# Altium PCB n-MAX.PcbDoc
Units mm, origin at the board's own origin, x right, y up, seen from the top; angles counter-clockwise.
Board outline 33.02 x 43.18 mm, 4 copper layers (Top Layer, 3.3V_PLANE, GND_PLANE, Bottom Layer); 27 components, 85 nets, 204 pads, 102 vias.
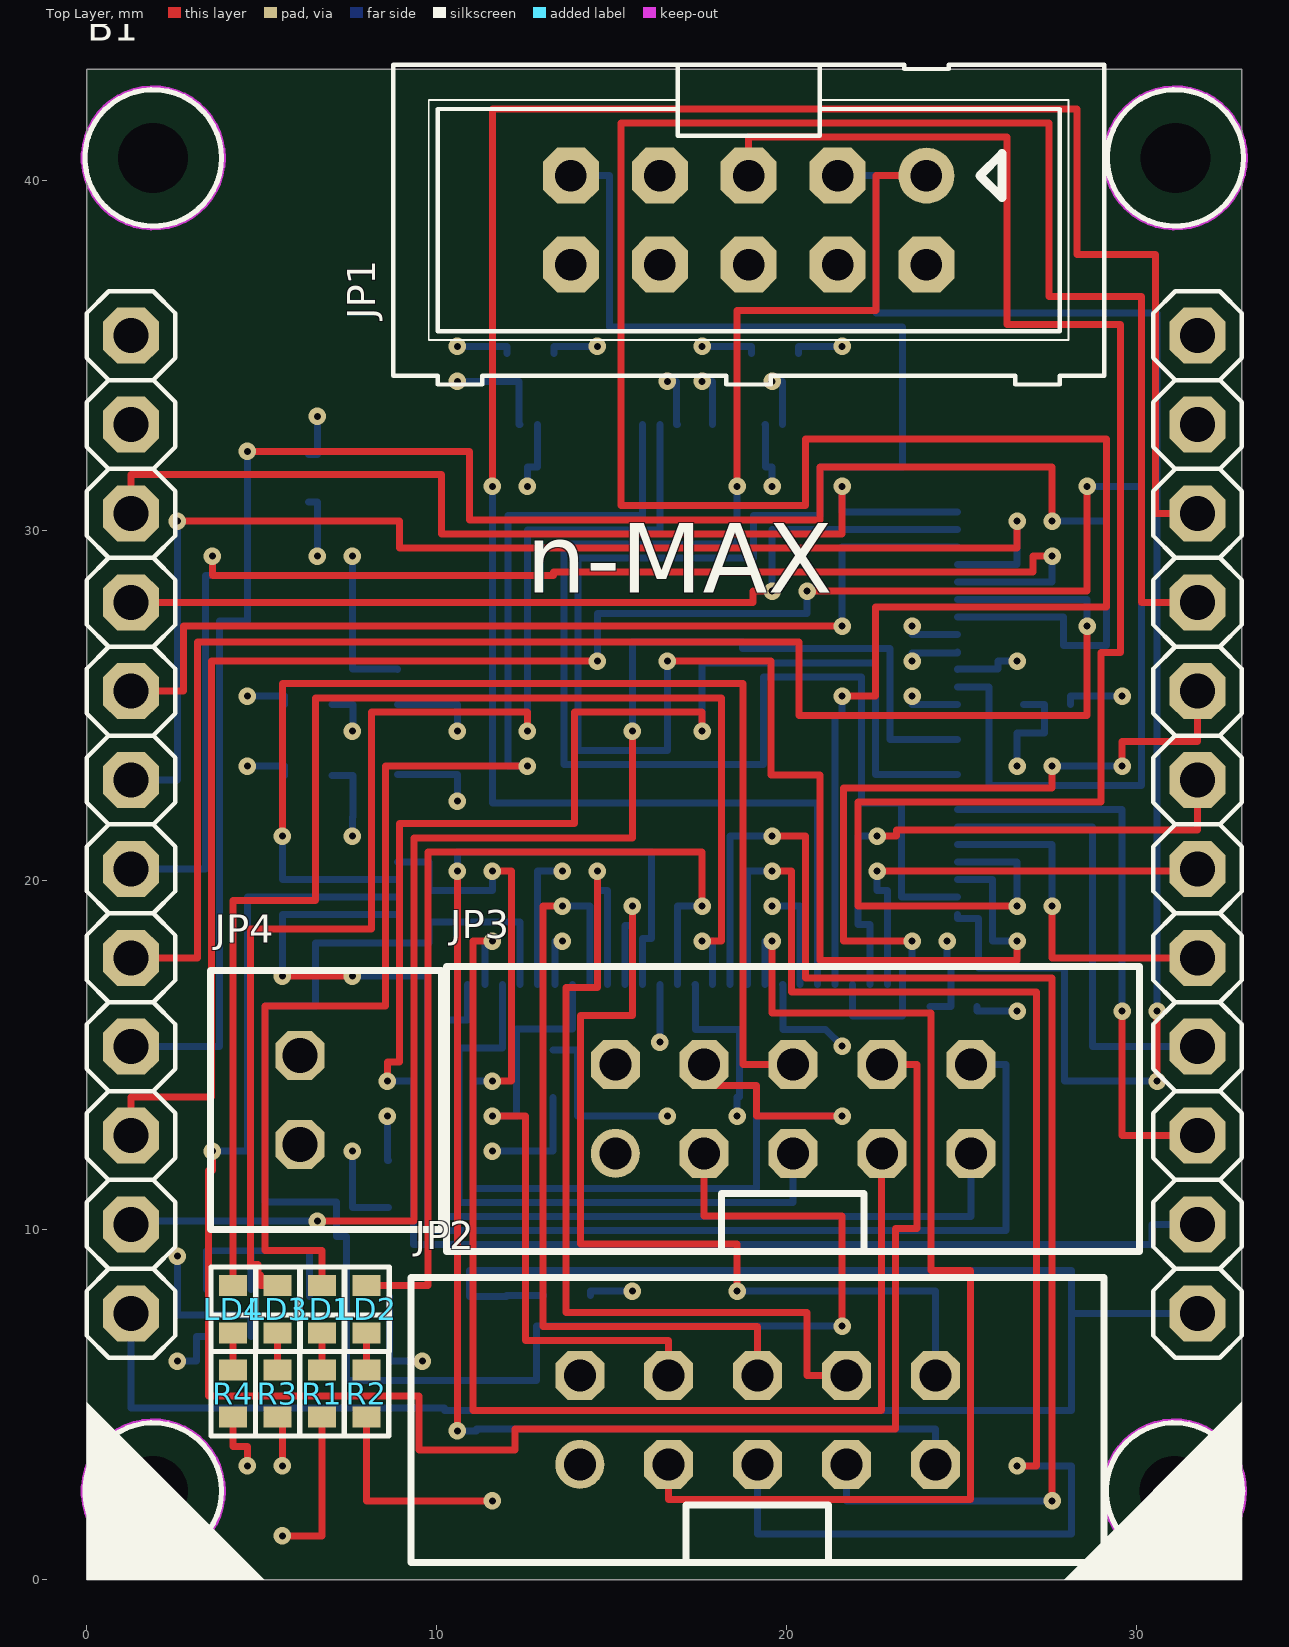
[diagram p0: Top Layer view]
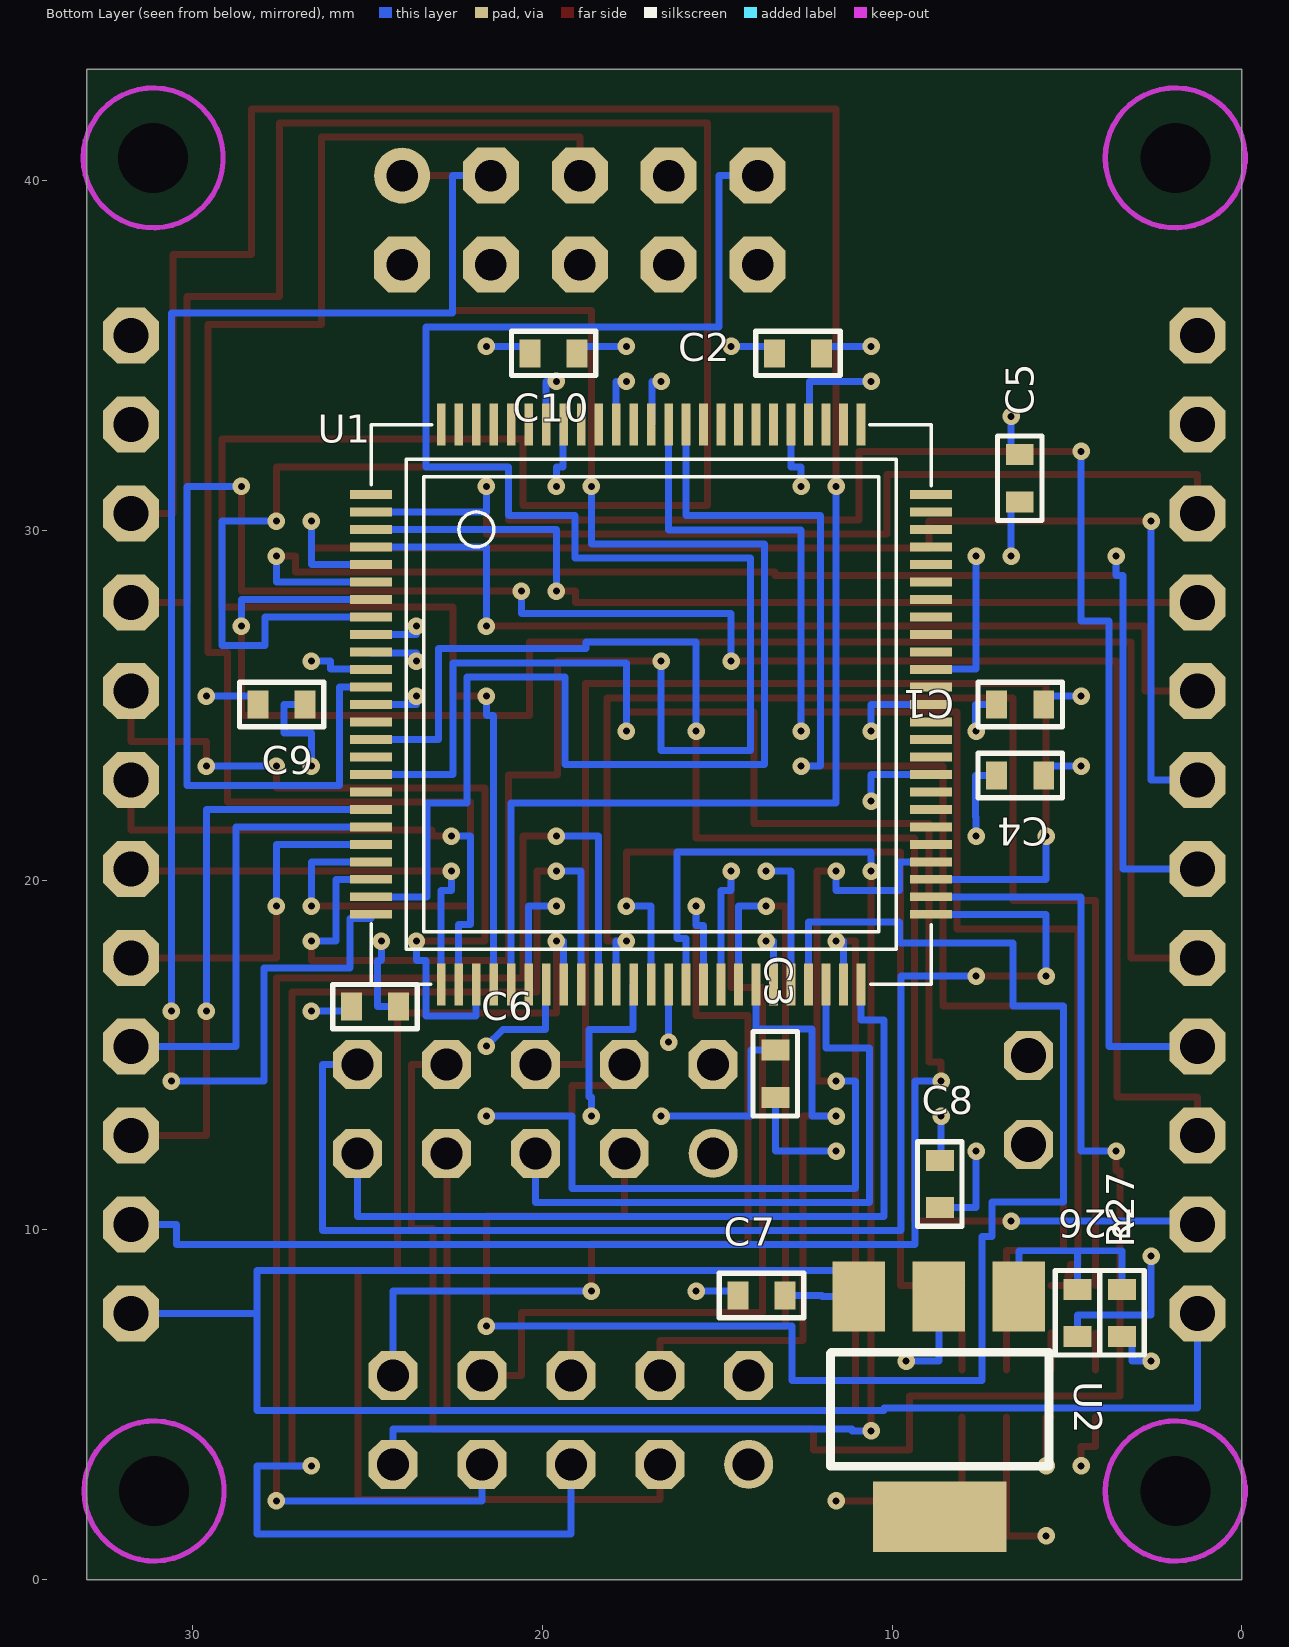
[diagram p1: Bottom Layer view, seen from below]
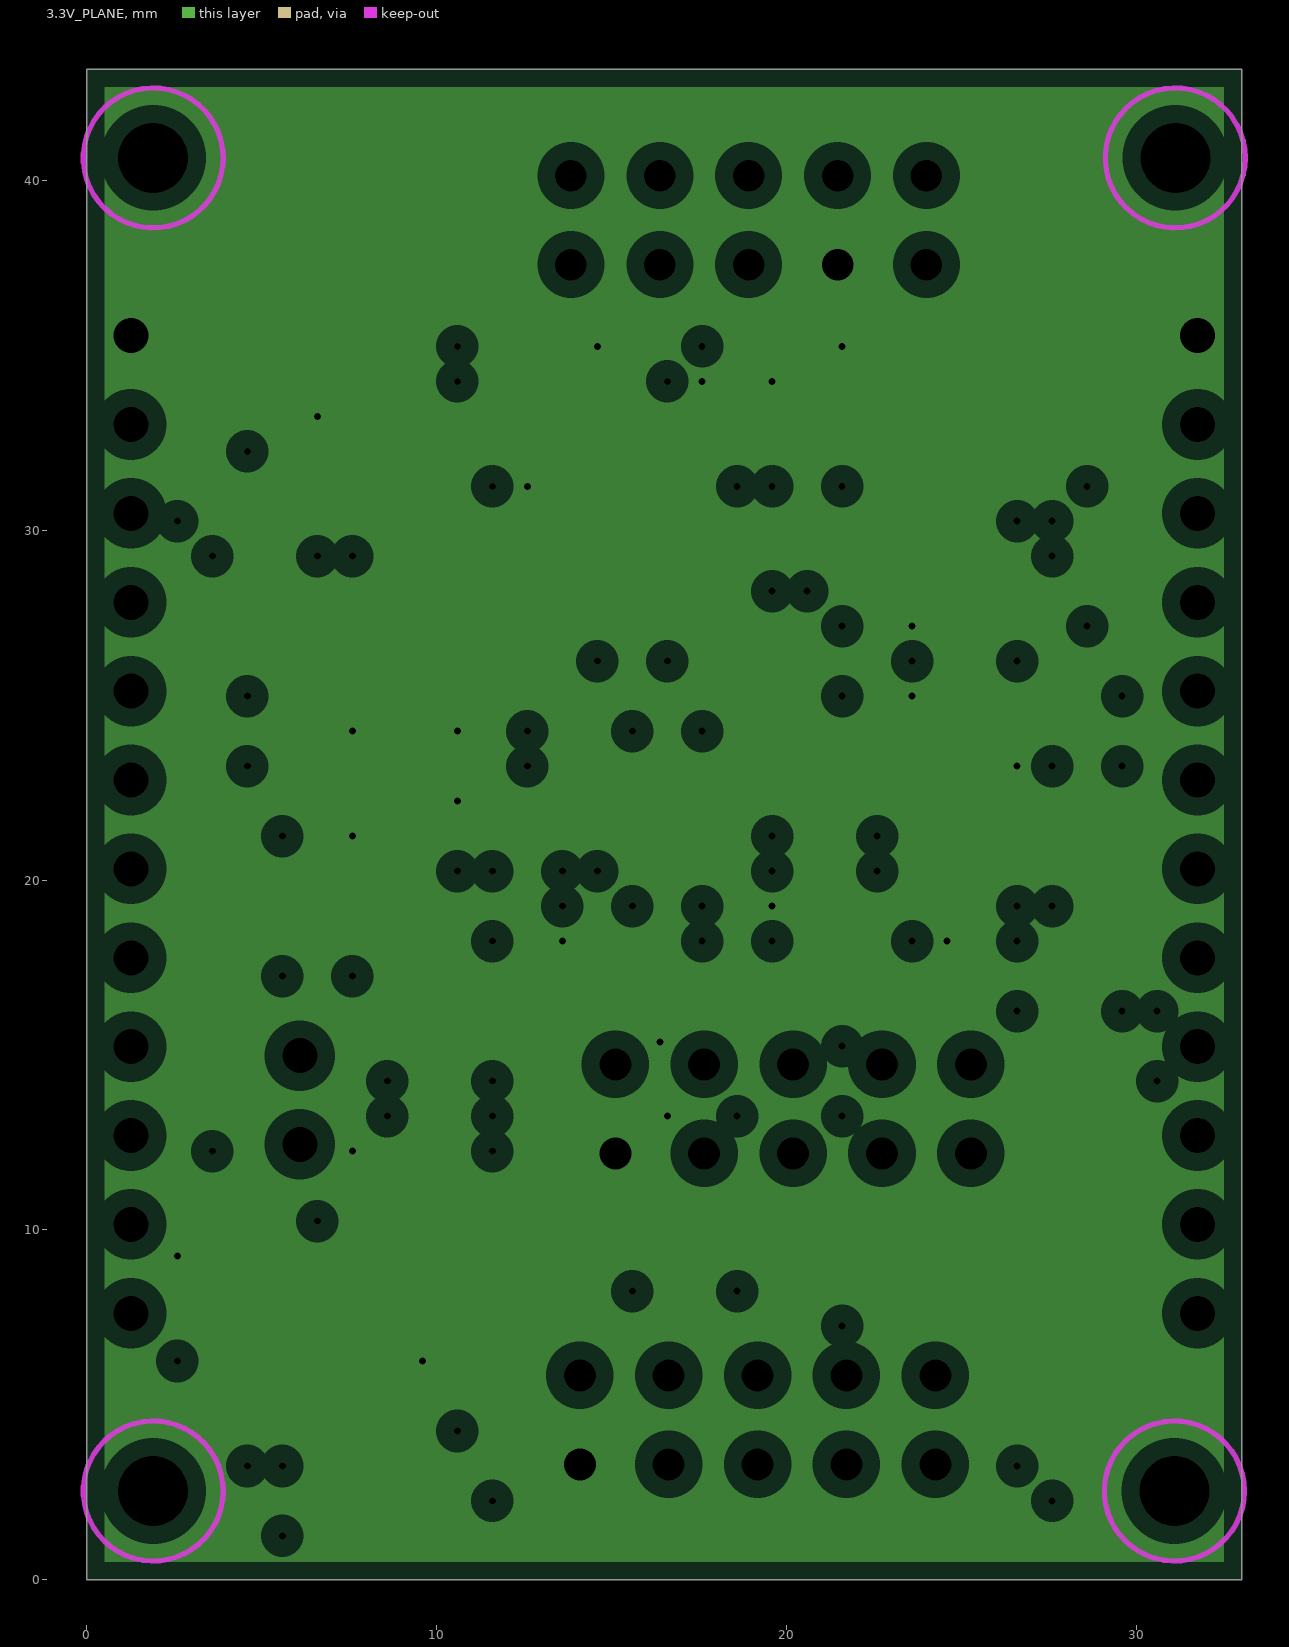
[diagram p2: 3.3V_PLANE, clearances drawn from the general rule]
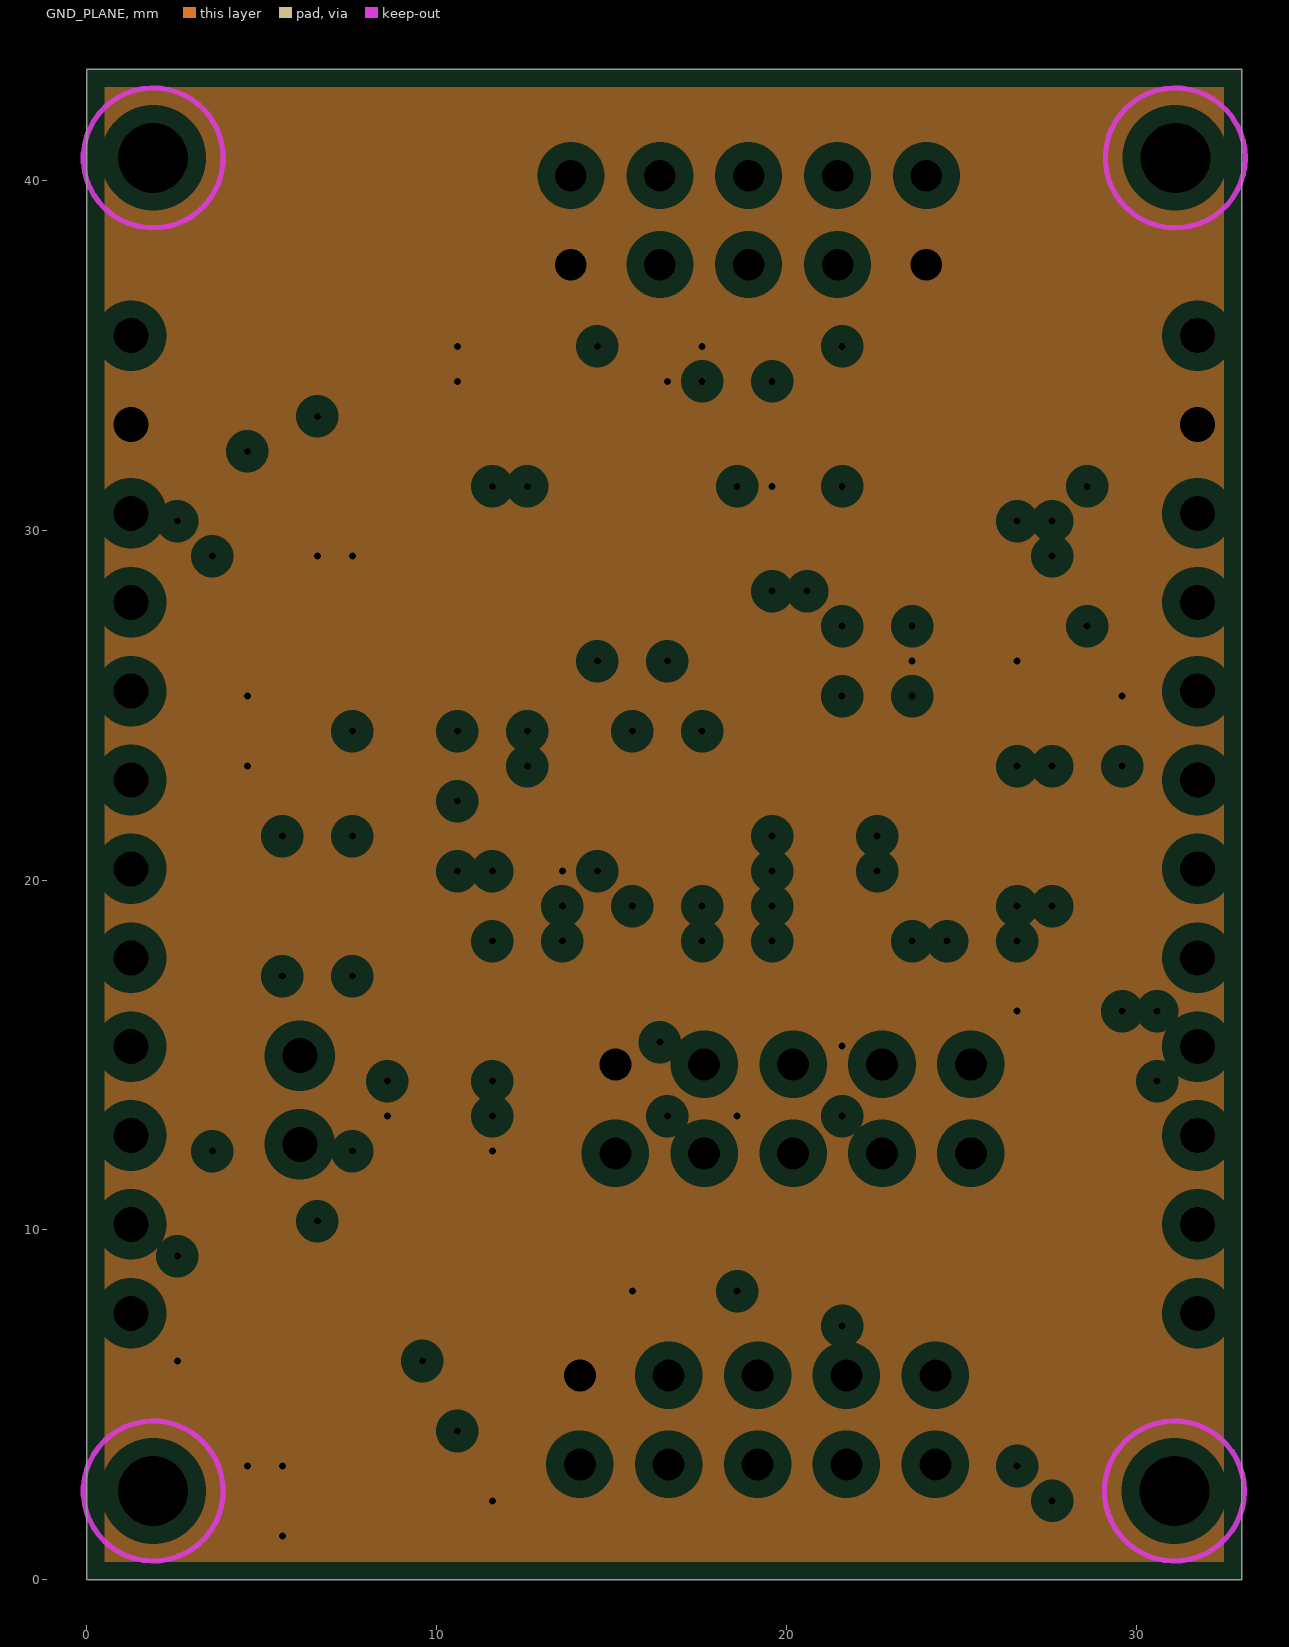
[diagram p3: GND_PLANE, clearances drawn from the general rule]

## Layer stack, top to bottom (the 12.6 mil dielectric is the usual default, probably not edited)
Top Solder: solder mask 0.0102, Solder Resist, Dk 3.5
Top Layer: signal copper 0.0356
Dielectric1: core 0.32, FR-4, Dk 4.8
3.3V_PLANE: plane copper 0.036, net 3.3V
Dielectric2: prepreg 0.32, FR-4, Dk 4.8
GND_PLANE: plane copper 0.036, net GND
Dielectric3: core 0.32, FR-4, Dk 4.8
Bottom Layer: signal copper 0.0356
Bottom Solder: solder mask 0.0102, Solder Resist, Dk 3.5

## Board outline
0,0 33.02,0 33.02,43.18 0,43.18

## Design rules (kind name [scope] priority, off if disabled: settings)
Clearance [All] p1: gap=0.2
ComponentClearance [All] p1 off: gap=0.254 collisioncheckmode=3 verticalgap=0.254 showdistances=FALSE
FabricationTestPointUsage TestPointUsage [All] p1: valid=0 allowmultiple=FALSE
FabricationTestpoint Testpoint [All] p1: side=3 testpointundercomponent=TRUE minsize=1.016 maxsize=2.54 preferedsize=1.524 minholesize=0 maxholesize=1.016 preferedholesize=0.813 testpointgrid=0.025 allowsidetop=TRUE allowsidebottom=TRUE usegrid=TRUE gridtolerance=0
HoleSize [All] p1: absolutevalues=TRUE maxlimit=8 minlimit=0 maxpercent=80.000 minpercent=20.000
PlaneClearance [All] p1: clearance=0.508
PlaneConnect [All] p1: planeconnectstyle=Relief reliefexpansion=0.508 reliefentries=4 reliefconductorwidth=0.254 reliefairgap=0.254
PolygonConnect [All] p1: connectstyle=Relief reliefconductorwidth=0.254 reliefentries=4 polygonreliefangle="90 Angle" airgapwidth=0.254
RoomDefinition n-MAX [InComponentClass('n-MAX')] p1: confinementstyle=ConfineIn formatcopy=TRUE lockcomponents=FALSE outline 34.163,-0.635 0,-0.635 0,-15.494 34.163,-15.494
RoutingVias [All] p1: holewidth=0.2 width=0.5 viastyle="Through Hole" minholewidth=0.2 minwidth=0.5 maxholewidth=2 maxwidth=2
SilkToSolderMaskClearance SilkscreenOverComponentPads [IsPad] p1: minsilkscreentomaskgap=0.254 clearancetoexposedcopper=TRUE
SolderMaskExpansion [All] p1: expansion=0.1
UnpouredPolygon [All] p1: allowunpoured=FALSE
Width [All] p1: maxlimit=1 minlimit=0.2 preferedwidth=0.2
22 further rules are at their usual default settings.

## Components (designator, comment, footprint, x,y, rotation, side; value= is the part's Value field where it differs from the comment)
B1 "N-GMS-CONNECTORS" N-GMS 1.27,40.64 r270 top locked
C1 "100nF" 0603_CAP 6.35,25.019 r180 bottom
C2 "100nF" 0603_CAP 12.7,35.052 r180 bottom
C3 "100nF" 0603_CAP 13.335,14.478 r270 bottom
C4 "100nF" 0603_CAP 6.35,22.987 r180 bottom
C5 "100nF" 0603_CAP 6.35,31.496 r270 bottom
C6 "100nF" 0603_CAP 24.765,16.383 r0 bottom
C7 "10uF/MLCC" 0603_CAP 13.716,8.128 r0 bottom
C8 "10uF/MLCC" 0603_CAP 8.636,11.303 r90 bottom
C9 "100nF" 0603_CAP 27.432,25.019 r0 bottom
C10 "100nF" 0603_CAP 19.685,35.052 r180 bottom
JP1 "Header 5X2" ML10 18.923,38.862 r180 top
JP2 "Header 5X2" ML10-FCI 19.177,4.572 r0 top
JP3 "Header 5X2" ML10-FCI 20.193,13.462 r0 top
JP4 "Header 2" MOLEX-705430001 6.096,14.986 r270 top
LD1 "LED" 0603_LED_RED 6.731,7.747 r270 top
LD2 "LED" 0603_LED_RED 8.001,7.747 r270 top
LD3 "LED" 0603_LED_RED 5.461,7.747 r270 top
LD4 "LED" 0603_LED_RED 4.191,7.747 r270 top
R1 "1K" 0603_res 6.731,5.334 r270 top
R2 "1K" 0603_res 8.001,5.334 r270 top
R3 "1K" 0603_res 5.461,5.334 r270 top
R4 "1K" 0603_res 4.191,5.334 r270 top
R26 "240R 1%" 0603_RES 4.699,7.62 r90 bottom
R27 "390R 1%" 0603_RES 3.429,7.62 r90 bottom
U1 "EPM240T100" TQFP100 24.88,33.02 r270 bottom
U2 "LM1117MPX-ADJ" SOT-223 8.636,4.953 r0 bottom

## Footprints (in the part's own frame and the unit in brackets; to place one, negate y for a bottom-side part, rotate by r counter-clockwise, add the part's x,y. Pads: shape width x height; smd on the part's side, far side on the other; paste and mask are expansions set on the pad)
0603_CAP [mm]
  rect 0.6x0.8 smd: 1(-0.66,0) 2(0.686,0)
  silkscreen extent -1.19,-0.64 1.22,0.64, body extent -0.8,-0.4 0.8,0.4, height 0.3
0603_LED_RED [mm]
  rect 0.6x0.8 smd: 1(-0.66,0) 2(0.686,0)
  silkscreen extent -1.19,-0.64 1.22,0.65, body extent -0.81,-0.4 0.81,0.4, height 0.6
0603_res [mm]
  rect 0.6x0.8 smd: 1(-0.66,0) 2(0.686,0)
  silkscreen extent -1.19,-0.64 1.22,0.64, body extent -0.8,-0.4 0.8,0.4, height 0.3
0603_RES [mm]
  rect 0.6x0.8 smd: 1(-0.66,0) 2(0.686,0)
  silkscreen extent -1.19,-0.64 1.22,0.64, body extent -0.8,-0.4 0.8,0.4, height 0.3
ML10 [mil]
  round 63 hole 35.43: 1(-200,-50)
  oct 63x63 hole 35.43: 2(-200,50) 3(-100,-50) 4(-100,50) 5(0,-50) 6(0,50) 7(100,-50) 8(100,50) 9(200,-50) 10(200,50)
  silkscreen extent -400,-175 400,185
ML10-FCI [mm]
  round 1.4 hole 0.914: 1(-5.08,-1.27)
  oct 1.4x1.4 hole 0.914: 2(-5.08,1.27) 3(-2.54,-1.27) 4(-2.54,1.27) 5(0,-1.27) 6(0,1.27) 7(2.54,-1.27) 8(2.54,1.27) 9(5.08,-1.27) 10(5.08,1.27)
  silkscreen extent -9.9,-4.08 9.9,4.08, body extent -9.91,-4.06 9.91,4.06, height 9.44
MOLEX-705430001 [mm]
  oct 1.4x1.4 hole 1 paste+0: 1(0,0) 2(2.54,0)
  silkscreen extent -2.42,-2.55 4.97,4.05, body extent -2.41,-2.54 4.95,4.06, height 11.81
N-GMS [mil]
  round 39.37 hole 78.74 paste+0: 0(0,1175) 0(0,25) 0(1500,1174) 0(1500,25)
  oct 63x63 hole 39.37: 1(200,0) 2(300,0) 3(400,0) 4(500,0) 5(600,0) 6(700,0) 7(800,0) 8(900,0) 9(1000,0) 10(1100,0) 11(1200,0) 12(1300,0) 13(1300,1200) 14(1200,1200) 15(1100,1200) 16(1000,1200) 17(900,1200) 18(800,1200) 19(700,1200) 20(600,1200) 21(500,1200) 22(400,1200) 23(300,1200) 24(200,1200)
  Keep-Out Layer circle w5.91: c1500,1174 r78.74
  Keep-Out Layer circle w5.91: c0,1175 r78.74
  Keep-Out Layer circle w5.91: c0,25 r78.74
  Keep-Out Layer circle w5.91: c1500,25 r78.74
  silkscreen extent -77,-52 1600,1252, body extent -75,-51 1577,1251, height 335
SOT-223 [mil]
  rect 59x79 smd: 1(-89,-124) 2(1,-124) 3(91,-124)
  rect 150x79 smd: 4(0,124)
  silkscreen extent -123,-61 123,67
TQFP100 [mm]
  rect 0.25x1.2 smd: 1(2,-0.005) 2(2.5,-0.005) 3(3,-0.005) 4(3.5,-0.005) 5(4,-0.005) 6(4.5,-0.005) 7(5,-0.005) 8(5.5,-0.005) 9(6,-0.005) 10(6.5,-0.005) 11(7,-0.005) 12(7.5,-0.005) 13(8,-0.005) 14(8.5,-0.005) 15(9,-0.005) 16(9.5,-0.005) 17(10,-0.005) 18(10.5,-0.005) 19(11,-0.005) 20(11.5,-0.005) 21(12,-0.005) 22(12.5,-0.005) 23(13,-0.005) 24(13.5,-0.005) 25(14,-0.005) 51(14,15.995) 52(13.5,15.995) 53(13,15.995) 54(12.5,15.995) 55(12,15.995) 56(11.5,15.995) 57(11,15.995) 58(10.5,15.995) 59(10,15.995) 60(9.5,15.995) 61(9,15.995) 62(8.5,15.995) 63(8,15.995) 64(7.5,15.995) 65(7,15.995) 66(6.5,15.995) 67(6,15.995) 68(5.5,15.995) 69(5,15.995) 70(4.5,15.995) 71(4,15.995) 72(3.5,15.995) 73(3,15.995) 74(2.5,15.995) 75(2,15.995)
  rect 1.2x0.25 smd: 26(16,1.995) 27(16,2.495) 28(16,2.995) 29(16,3.495) 30(16,3.995) 31(16,4.495) 32(16,4.995) 33(16,5.495) 34(16,5.995) 35(16,6.495) 36(16,6.995) 37(16,7.495) 38(16,7.995) 39(16,8.495) 40(16,8.995) 41(16,9.495) 42(16,9.995) 43(16,10.495) 44(16,10.995) 45(16,11.495) 46(16,11.995) 47(16,12.495) 48(16,12.995) 49(16,13.495) 50(16,13.995) 76(0,13.995) 77(0,13.495) 78(0,12.995) 79(0,12.495) 80(0,11.995) 81(0,11.495) 82(0,10.995) 83(0,10.495) 84(0,9.995) 85(0,9.495) 86(0,8.995) 87(0,8.495) 88(0,7.995) 89(0,7.495) 90(0,6.995) 91(0,6.495) 92(0,5.995) 93(0,5.495) 94(0,4.995) 95(0,4.495) 96(0,3.995) 97(0,3.495) 98(0,2.995) 99(0,2.495) 100(0,1.995)
  silkscreen extent 0,0 16,16, body extent 0.45,0.45 15.46,15.46, height 1.74

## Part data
C1 C2 C3 C4 C5 C6 C7 C8 C9 C10: library part C, "CAPACITOR"
JP1 JP2 JP3: "Header, 5-Pin, Dual row"
JP4: "Header, 2-Pin"
R1 R2 R3 R4 R26 R27: library part R, "RESISTOR"
U2: library part LM1117, "REGULATOR LOW DROPOUT"

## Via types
v1: diameter 0.5, hole 0.2, Top Layer to Bottom Layer, 102 vias

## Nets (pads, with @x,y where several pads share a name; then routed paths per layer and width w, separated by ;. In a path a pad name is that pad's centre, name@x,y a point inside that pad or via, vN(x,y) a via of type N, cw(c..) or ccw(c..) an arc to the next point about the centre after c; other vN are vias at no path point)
1: B1.3 U1.2 | length 28.5
  Top Layer w0.2: B1.3 1.27,31.585 10.146,31.585 10.146,29.895 21.596,29.895 v1(21.596,31.255)
  Bottom Layer w0.2: v1(21.596,31.255) 21.596,30.52 U1.2
2: B1.4 U1.3 | length 25.7
  Top Layer w0.2: B1.4 19.046,27.94 19.046,28.255 v1(19.596,28.255)
  Bottom Layer w0.2: v1(19.596,28.255) 19.596,30.02 U1.3
3: B1.5 U1.4 | length 27.7
  Top Layer w0.2: B1.5 2.776,25.4 2.776,27.255 v1(21.596,27.255)
  Bottom Layer w0.2: v1(21.596,27.255) 21.596,29.52 U1.4
3.3V: B1.1 B1.24 C1.1 C2.1 C3.1 C4.1 C5.1 C6.1 C8.1 C9.1 C10.1 JP1.4 JP2.1 JP3.1 R26.1 U1.9 U1.13 U1.31 U1.39 U1.45 U1.59 U1.63 U1.80 U1.90 U1.94 U2.2 | length 47.9
  Bottom Layer w0.2: v1(2.596,9.255) 2.596,7.565 4.699,7.565 R26.1 ; C5.1 6.596,32.156 v1(6.596,33.255) ; C4.1 7.616,22.987 7.616,21.805 7.596,21.805 v1(7.596,21.255) ; C1.1 7.616,25.019 7.616,24.255 v1(7.596,24.255) ; v1(7.596,12.255) 7.596,10.643 C8.1 ; U2.2 8.661,6.255 v1(9.596,6.255) ; U1.59 10.596,23.02 v1(10.596,22.255) ; U1.63 10.596,25.02 v1(10.596,24.255) ; v1(12.596,31.255) 12.596,31.805 12.885,31.805 U1.80 ; C3.1 14.036,15.138 14.036,13.255 v1(16.596,13.255) ; C2.1 13.36,35.255 v1(14.596,35.255) ; U1.45 13.385,18.255 v1(13.596,18.255) ; v1(16.383,15.367) 16.383,17.018 U1.39 ; v1(17.596,34.255) 17.885,34.255 U1.90 ; v1(19.596,19.255) 20.385,19.255 U1.31 ; v1(19.596,34.255) 19.885,34.255 U1.94 ; C10.1 20.345,35.255 v1(21.596,35.255) ; v1(23.596,25.255) 23.596,25.02 U1.13 ; v1(23.596,27.255) 23.596,27.02 U1.9 ; C6.1 24.706,16.383 24.706,17.705 24.596,17.705 v1(24.596,18.255) ; v1(26.596,23.255) 26.596,24.205 27.376,24.205 27.376,25.019 C9.1
4: B1.6 U1.5 | length 37.2
  Top Layer w0.2: v1(2.596,30.255) 8.946,30.255 8.946,29.495 26.596,29.495 v1(26.596,30.255)
  Bottom Layer w0.2: B1.6 2.596,22.86 v1(2.596,30.255) ; U1.5 26.596,29.02 v1(26.596,30.255)
5: B1.7 U1.6 | length 39.8
  Top Layer w0.2: v1(3.596,29.255) 3.596,28.705 13.346,28.705 13.346,28.805 27.046,28.805 27.046,29.255 v1(27.596,29.255)
  Bottom Layer w0.2: B1.7 3.396,20.32 3.396,28.705 3.596,28.705 v1(3.596,29.255) ; U1.6 27.596,28.52 v1(27.596,29.255)
5V: B1.12 B1.13 C7.1 U2.3 | length 57.3
  Bottom Layer w0.2: B1.12 1.27,4.915 10.226,4.915 10.226,4.835 28.146,4.835 28.146,7.62 ; C7.1 12.006,8.128 12.006,8.103 U2.3 10.947,8.835 28.146,8.835 28.146,7.62 ; B1.13 28.146,7.62
6: B1.8 U1.7 | length 45.5
  Top Layer w0.2: B1.8 3.176,17.78 3.176,26.805 20.356,26.805 20.356,24.705 28.596,24.705 v1(28.596,27.255)
  Bottom Layer w0.2: U1.7 28.596,28.02 v1(28.596,27.255)
7: B1.9 U1.8 | length 58.5
  Top Layer w0.2: v1(4.596,32.255) 10.946,32.255 10.946,30.295 20.956,30.295 20.956,31.805 27.596,31.805 v1(27.596,30.255)
  Bottom Layer w0.2: B1.9 3.796,15.24 3.796,27.405 4.596,27.405 v1(4.596,32.255) ; U1.8 27.926,27.52 27.926,26.705 29.146,26.705 29.146,30.255 v1(27.596,30.255)
8: B1.10 U1.12 | length 64.1
  Top Layer w0.2: B1.10 1.27,13.805 3.576,13.805 3.576,26.255 v1(14.596,26.255) ; v1(20.596,28.255) 28.596,28.255 v1(28.596,31.255)
  Bottom Layer w0.2: v1(14.596,26.255) 14.596,27.615 20.596,27.615 v1(20.596,28.255) ; U1.12 25.786,25.52 25.786,22.705 30.146,22.705 30.146,31.255 v1(28.596,31.255)
9: B1.11 U1.15 | length 43
  Top Layer w0.2: v1(6.596,10.255) 9.356,10.255 9.356,21.205 15.596,21.205 v1(15.596,24.255)
  Bottom Layer w0.2: B1.11 1.27,10.255 v1(6.596,10.255) ; v1(15.596,24.255) 15.596,26.805 18.746,26.805 18.746,26.615 22.956,26.615 22.956,24.02 U1.15
10: B1.14 U1.17 | length 60.9
  Top Layer w0.2: v1(8.596,14.255) 8.596,14.805 8.95,14.805 8.95,21.615 13.946,21.615 13.946,24.805 17.596,24.805 v1(17.596,24.255)
  Bottom Layer w0.2: v1(8.596,14.255) 9.346,14.255 9.346,9.585 30.456,9.585 30.456,10.16 B1.14 ; v1(17.596,24.255) 17.596,26.208 22.549,26.208 22.549,23.02 U1.17
11: B1.15 U1.19 | length 16.2
  Top Layer w0.2: v1(29.596,16.255) 29.596,12.7 B1.15
  Bottom Layer w0.2: U1.19 29.596,22.02 v1(29.596,16.255)
12: B1.16 U1.20 | length 13.1
  Bottom Layer w0.2: U1.20 28.756,21.52 28.756,15.24 B1.16
13: B1.17 U1.21 | length 10.1
  Top Layer w0.2: v1(27.596,19.255) 27.596,17.78 B1.17
  Bottom Layer w0.2: U1.21 27.596,21.02 v1(27.596,19.255)
14: B1.18 U1.26 | length 12.7
  Top Layer w0.2: v1(22.596,20.255) 31.75,20.255 B1.18
  Bottom Layer w0.2: v1(22.596,20.255) 22.596,19.705 22.885,19.705 U1.26
15: B1.19 U1.27 | length 15.9
  Top Layer w0.2: v1(22.596,21.255) 23.146,21.255 23.146,21.425 31.75,21.425 B1.19
  Bottom Layer w0.2: U1.27 22.385,18.725 22.046,18.725 22.046,21.255 v1(22.596,21.255)
16: B1.20 U1.28 | length 24
  Top Layer w0.2: v1(23.596,18.255) 21.636,18.255 21.636,22.625 27.596,22.625 v1(27.596,23.255) ; v1(29.596,23.255) 29.596,23.965 31.75,23.965 B1.20
  Bottom Layer w0.2: U1.28 21.885,16.115 23.316,16.115 23.316,17.705 23.596,17.705 v1(23.596,18.255) ; v1(27.596,23.255) v1(29.596,23.255)
17: B1.21 U1.29 | length 80.2
  Top Layer w0.2: v1(21.596,25.255) 22.546,25.255 22.546,27.805 29.146,27.805 29.146,32.605 20.546,32.605 20.546,30.705 15.276,30.705 15.276,41.635 27.506,41.635 27.506,36.675 30.146,36.675 30.146,27.94 B1.21
  Bottom Layer w0.2: U1.29 21.385,24.705 21.596,24.705 v1(21.596,25.255)
18: B1.22 U1.30 | length 66
  Top Layer w0.2: v1(11.596,31.255) 11.596,42.035 28.306,42.035 28.306,37.875 30.546,37.875 30.546,30.48 B1.22
  Bottom Layer w0.2: v1(11.596,31.255) 11.596,22.205 20.885,22.205 U1.30
19: JP2.3 U1.33 | length 32.7
  Top Layer w0.2: JP2.3 16.637,2.295 25.266,2.295 25.266,8.845 24.136,8.845 24.136,16.205 19.596,16.205 v1(19.596,18.255)
  Bottom Layer w0.2: U1.33 19.385,18.255 v1(19.596,18.255)
20: JP2.5 U1.34 | length 43.5
  Top Layer w0.2: v1(19.596,20.255) 20.146,20.255 20.146,16.805 27.146,16.805 27.146,3.255 v1(26.596,3.255)
  Bottom Layer w0.2: U1.34 18.885,20.255 v1(19.596,20.255) ; JP2.5 19.177,1.305 28.146,1.305 28.146,3.255 v1(26.596,3.255)
21: JP2.7 U1.35 | length 39.4
  Top Layer w0.2: v1(19.596,21.255) 20.546,21.255 20.546,17.205 27.596,17.205 v1(27.596,2.255)
  Bottom Layer w0.2: U1.35 18.385,21.255 v1(19.596,21.255) ; JP2.7 21.717,2.255 v1(27.596,2.255)
22: JP2.9 U1.40 | length 40.9
  Top Layer w0.2: v1(10.596,4.255) v1(10.596,20.255)
  Bottom Layer w0.2: v1(10.596,4.255) 11.146,4.255 11.146,4.305 24.257,4.305 JP2.9 ; v1(10.596,20.255) 10.596,20.805 16.146,20.805 16.146,18.325 15.885,18.325 U1.40
23: JP2.10 U1.41 | length 27.5
  Top Layer w0.2: v1(15.596,19.255) 15.596,16.135 14.111,16.135 14.111,9.605 18.596,9.605 v1(18.596,8.255)
  Bottom Layer w0.2: U1.41 15.385,18.705 15.596,18.705 v1(15.596,19.255) ; v1(18.596,8.255) 24.257,8.255 JP2.10
24: JP2.8 U1.42 | length 26.8
  Top Layer w0.2: v1(14.596,20.255) 14.596,16.935 13.706,16.935 13.706,7.645 20.586,7.645 20.586,5.842 JP2.8
  Bottom Layer w0.2: v1(14.596,20.255) 14.596,19.705 14.885,19.705 U1.42
25: JP2.6 U1.43 | length 23.1
  Top Layer w0.2: v1(13.596,19.255) 13.046,19.255 13.046,7.245 19.177,7.245 JP2.6
  Bottom Layer w0.2: v1(13.596,19.255) 14.385,19.255 U1.43
26: JP2.4 U1.44 | length 18.5
  Top Layer w0.2: v1(11.596,13.255) 12.546,13.255 12.546,6.845 16.637,6.845 JP2.4
  Bottom Layer w0.2: v1(11.596,13.255) 12.286,13.255 12.286,15.745 13.885,15.745 U1.44
27: JP3.3 U1.47 | length 49.1
  Top Layer w0.2: JP3.3 17.653,10.405 21.596,10.405 v1(21.596,7.255)
  Bottom Layer w0.2: U1.47 12.385,18.805 9.786,18.805 9.786,18.205 6.546,18.205 6.546,16.395 5.096,16.395 5.096,10.805 7.146,10.805 7.146,9.815 7.426,9.815 7.426,5.705 12.856,5.705 12.856,7.255 v1(21.596,7.255)
28: JP3.5 U1.48 | length 18.4
  Bottom Layer w0.2: U1.48 11.885,15.205 10.643,15.205 10.643,10.79 20.193,10.79 JP3.5
29: JP3.7 U1.49 | length 34.5
  Top Layer w0.2: v1(11.596,18.255) 11.046,18.255 11.046,4.835 22.726,4.835 22.726,12.192 JP3.7
  Bottom Layer w0.2: U1.49 11.385,18.255 v1(11.596,18.255)
30: JP3.9 U1.50 | length 24.1
  Bottom Layer w0.2: U1.50 10.885,16.005 10.236,16.005 10.236,10.388 25.273,10.388 JP3.9
31: JP3.10 U1.51 | length 38.8
  Top Layer w0.2: v1(5.596,17.255) v1(7.596,17.255)
  Bottom Layer w0.2: v1(5.596,17.255) 5.596,19.02 U1.51 ; v1(7.596,17.255) 9.746,17.255 9.746,9.985 26.276,9.985 26.276,14.732 JP3.10
32: JP3.8 U1.52 | length 53.5
  Top Layer w0.2: v1(3.596,12.255) 3.596,11.705 3.486,11.705 3.486,5.255 9.506,5.255 9.506,3.705 12.246,3.705 12.246,4.305 23.126,4.305 23.126,10.045 23.736,10.045 23.736,14.732 JP3.8
  Bottom Layer w0.2: v1(3.596,12.255) 4.596,12.255 4.596,19.52 U1.52
33: JP3.6 U1.53 | length 34.4
  Top Layer w0.2: v1(5.596,21.255) 5.596,25.615 18.756,25.615 18.756,14.732 JP3.6
  Bottom Layer w0.2: v1(5.596,21.255) 5.596,20.02 U1.53
34: JP3.4 U1.54 | length 32.8
  Top Layer w0.2: v1(11.596,14.255) 12.147,14.255 12.147,20.255 v1(11.596,20.255) ; JP3.4 17.653,14.132 19.147,14.132 19.147,13.255 v1(21.596,13.255)
  Bottom Layer w0.2: U1.54 9.786,20.52 9.786,19.705 11.596,19.705 v1(11.596,20.255) ; v1(11.596,14.255) 11.045,14.255 11.045,11.192 19.147,11.192 19.147,13.255 v1(21.596,13.255)
35: U1.55
36: U1.56
37: U1.57
38: U1.60
39: U1.61
40: U1.62
41: U1.64
42: U1.66
43: U1.67
44: U1.68
45: U1.69
46: U1.70
47: U1.71
48: U1.72
49: U1.73
50: U1.74
51: U1.75
52: U1.76
53: U1.77
54: U1.78
55: U1.81
56: U1.82
57: U1.83
58: U1.84
59: U1.85
60: U1.89
61: U1.91
62: U1.92
63: U1.95
64: U1.96
65: U1.97
66: U1.98
67: U1.99
68: U1.100
69: U1.1
CLK: JP1.1 U1.24 | length 47.2
  Top Layer w0.2: v1(18.596,31.255) 18.596,36.275 22.566,36.275 22.566,40.132 JP1.1
  Bottom Layer w0.2: v1(18.596,31.255) 18.596,29.605 13.646,29.605 13.646,23.305 19.346,23.305 19.346,25.805 22.146,25.805 22.146,22.205 23.286,22.205 23.286,19.52 U1.24
GND: B1.2 B1.23 C1.2 C2.2 C3.2 C4.2 C5.2 C6.2 C7.2 C8.2 C9.2 C10.2 JP1.2 JP1.10 JP2.2 JP3.2 R1.2 R2.2 R3.2 R4.2 R27.1 U1.10 U1.11 U1.32 U1.37 U1.46 U1.65 U1.79 U1.88 U1.93 | length 58.7
  Top Layer w0.2: R4.2 4.191,3.805 4.596,3.805 v1(4.596,3.255) ; R3.2 5.596,4.648 v1(5.596,3.255) ; v1(5.596,1.255) 6.731,1.255 R1.2 ; R2.2 8.001,2.255 v1(11.596,2.255)
  Bottom Layer w0.2: v1(2.596,6.255) 3.136,6.255 3.136,6.96 R27.1 ; v1(4.596,23.255) 5.664,23.255 C4.2 ; v1(4.596,25.255) 5.664,25.255 C1.2 ; C5.2 6.596,30.81 v1(6.596,29.255) ; v1(7.596,29.255) 7.596,26.035 8.885,26.035 U1.65 ; v1(8.596,13.255) 8.596,11.989 C8.2 ; v1(10.596,34.255) 12.366,34.255 12.366,33.02 U1.79 ; v1(10.596,35.255) 12.014,35.255 C2.2 ; v1(11.596,12.255) 13.335,12.255 C3.2 ; U1.46 12.885,20.255 v1(13.596,20.255) ; C7.2 14.402,8.255 v1(15.596,8.255) ; v1(16.596,34.255) 16.866,34.255 16.866,33.02 U1.88 ; U1.37 17.406,17.02 17.406,15.735 18.656,15.735 18.656,13.805 18.596,13.805 v1(18.596,13.255) ; v1(17.596,35.255) 18.999,35.255 C10.2 ; U1.93 19.406,33.02 19.406,31.805 19.596,31.805 v1(19.596,31.255) ; U1.32 19.906,17.02 19.906,15.735 21.116,15.735 v1(21.596,15.255) ; v1(23.596,26.255) 23.596,26.495 24.885,26.495 U1.10 ; U1.11 24.885,26.035 26.046,26.035 26.046,26.255 v1(26.596,26.255) ; C6.2 25.451,16.255 v1(26.596,16.255) ; C9.2 28.118,25.255 v1(29.596,25.255)
LED0: LD1.1 U1.86 | length 38.1
  Top Layer w0.2: LD1.1 6.731,9.415 5.096,9.415 5.096,16.395 8.546,16.395 8.546,23.255 v1(12.596,23.255)
  Bottom Layer w0.2: v1(12.596,23.255) 12.046,23.255 12.046,30.415 15.885,30.415 U1.86
LED1: LD2.1 U1.38 | length 26.5
  Top Layer w0.2: LD2.1 9.756,8.407 9.756,20.805 17.596,20.805 v1(17.596,19.255)
  Bottom Layer w0.2: U1.38 16.885,19.255 v1(17.596,19.255)
LED2: LD3.1 U1.87 | length 38.2
  Top Layer w0.2: LD3.1 4.966,8.407 4.966,8.715 4.896,8.715 4.896,9.009 4.686,9.009 4.686,18.605 8.146,18.605 8.146,24.805 12.596,24.805 v1(12.596,24.255)
  Bottom Layer w0.2: v1(12.596,24.255) 12.596,30.012 16.385,30.012 U1.87
LED3: LD4.1 U1.36 | length 39.8
  Top Layer w0.2: LD4.1 4.191,19.415 6.546,19.415 6.546,25.208 18.146,25.208 18.146,18.255 v1(17.596,18.255)
  Bottom Layer w0.2: v1(17.596,18.255) 17.885,18.255 U1.36
NetLD1_2: LD1.2 R1.1 | length 1.1
  Top Layer w0.2: R1.1 LD1.2
NetLD2_2: LD2.2 R2.1 | length 1.1
  Top Layer w0.2: R2.1 LD2.2
NetLD3_2: LD3.2 R3.1 | length 1.1
  Top Layer w0.2: R3.1 LD3.2
NetLD4_2: LD4.2 R4.1 | length 1.1
  Top Layer w0.2: R4.1 LD4.2
NetR26_2: R26.2 R27.2 U2.1 | length 6.5
  Bottom Layer w0.2: R27.2 3.429,9.407 4.699,9.407 ; R26.2 4.699,9.407 ; U2.1 6.375,9.407 4.699,9.407
TDI: JP1.9 U1.23 | length 62.8
  Top Layer w0.2: v1(16.596,26.255) 19.556,26.255 19.556,23.005 20.956,23.005 20.956,17.705 26.596,17.705 v1(26.596,18.255)
  Bottom Layer w0.2: JP1.9 14.946,40.132 14.946,35.805 23.316,35.805 23.316,31.805 20.966,31.805 20.966,30.425 19.056,30.425 19.056,29.205 14.046,29.205 14.046,23.705 16.596,23.705 v1(16.596,26.255) ; U1.23 25.886,20.02 25.886,18.255 v1(26.596,18.255)
TDO: JP1.3 U1.25 | length 45.5
  Top Layer w0.2: v1(30.596,14.255) v1(30.596,16.255)
  Bottom Layer w0.2: JP1.3 22.566,40.132 22.566,36.205 30.596,36.205 v1(30.596,16.255) ; U1.25 24.885,18.895 25.486,18.895 25.486,17.485 27.946,17.485 27.946,14.255 v1(30.596,14.255)
TMS: JP1.5 U1.22 | length 48.7
  Top Layer w0.2: JP1.5 18.923,41.233 26.306,41.233 26.306,35.875 29.556,35.875 29.556,26.505 28.996,26.505 28.996,22.225 22.046,22.225 22.046,19.255 v1(26.596,19.255)
  Bottom Layer w0.2: U1.22 26.596,20.52 v1(26.596,19.255)
pads on no net: B1.0 JP1.6 JP1.7 JP1.8 JP4.1 JP4.2 U1.14 U1.16 U1.18 U1.58 U2.4

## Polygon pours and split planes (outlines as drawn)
GND on GND_PLANE (split plane): 32.51,0.51 0.51,0.51 0.51,42.67 32.51,42.67
3.3V on 3.3V_PLANE (split plane): 32.51,0.51 0.51,0.51 0.51,42.67 32.51,42.67

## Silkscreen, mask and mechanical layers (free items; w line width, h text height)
Bottom Solder:
  circle w1: c4.953,37.782 r1
  circle w0.508: c29.058,37.782 r1.2
  circle w1: c34.798,2.222 r1
  circle w0.508: c-0.762,2.222 r1.2
  region: 3.433,22.781 3.425,28.4 5.28,28.4 5.287,22.781 3.458,22.781
Mechanical 3:
  the board outline again, w0.15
